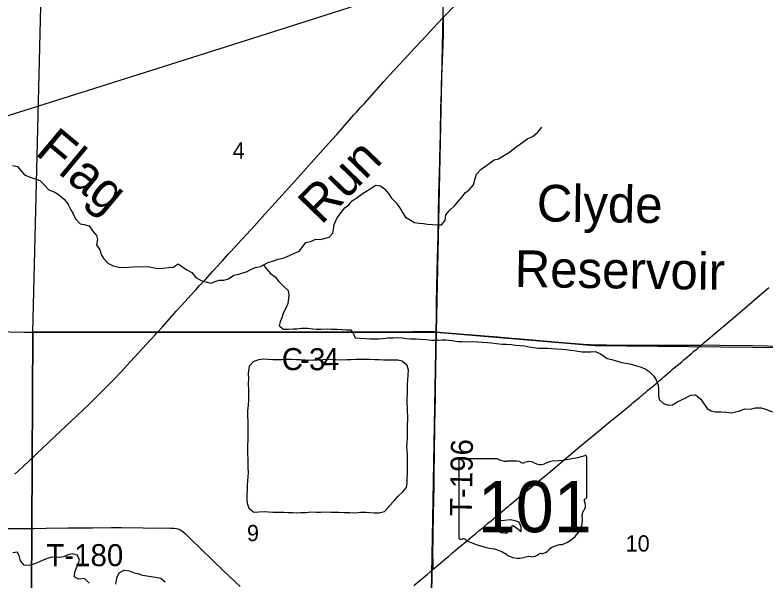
# Model space of a CAD drawing. Extents: x -8.5 to 18.7, y -20.3 to 7.
# Drawn here: x 3.109 to 6.975, y -13.956 to -11.043 of the extents above; entities that cross this region are included whole.
import ezdxf

# ---------------------------------------------------------------- set-up
doc = ezdxf.new("R2010")
doc.units = 0
for name, color, linetype in [('GM_X_County_Road', 7, 'Continuous'), ('GM_X_County_Road_Text', 7, 'Continuous'), ('GM_X_Minor_Lake', 7, 'Continuous'), ('GM_X_Minor_Lake_Text', 7, 'Continuous'), ('GM_X_Minor_River', 7, 'Continuous'), ('GM_X_Minor_River_Text', 7, 'Continuous'), ('GM_X_Rail_Line', 7, 'Continuous'), ('GM_X_Section', 7, 'Continuous'), ('GM_X_Section_Text', 7, 'Continuous'), ('GM_X_State_Location', 7, 'Continuous'), ('GM_X_State_Route', 7, 'Continuous'), ('GM_X_State_Shield', 7, 'Continuous'), ('GM_X_Township_Road', 7, 'Continuous'), ('GM_X_Township_Road_Text', 7, 'Continuous')]:
    doc.layers.add(name, color=color, linetype=linetype)

msp = doc.modelspace()

# ---------------------------------------------------------------- linework, layer by layer
at = {"layer": 'GM_X_County_Road'}
for points in [[(3.0069, -12.6754), (3.1591, -12.6774), (3.2088, -12.678), (3.2673, -12.6781), (3.3506, -12.6786), (3.3928, -12.6786), (3.4376, -12.6788), (3.4761, -12.6789), (3.4922, -12.6789), (3.5146, -12.6787), (3.5233, -12.6786), (3.537, -12.6783), (3.5754, -12.6787), (3.6127, -12.6782), (3.6782, -12.6782), (3.7482, -12.6772), (3.839, -12.6772), (3.8443, -12.6773)], [(3.8443, -12.6773), (3.9136, -12.6777), (4.0417, -12.6773), (4.1747, -12.6773), (4.2468, -12.6772), (4.3438, -12.6767), (4.4582, -12.6767), (4.5552, -12.6766), (4.6074, -12.6769), (4.7466, -12.677), (4.8535, -12.6762), (4.9207, -12.6761), (5.0052, -12.6759), (5.1557, -12.6755), (5.2203, -12.6751), (5.2689, -12.6755), (5.2805, -12.6762)], [(5.2805, -12.6762), (5.2969, -12.6779), (5.3167, -12.6796), (5.4209, -12.6881), (5.5981, -12.7028), (5.6699, -12.709), (5.738, -12.7149), (5.9114, -12.7301), (6.0402, -12.7408), (6.0761, -12.7426), (6.2401, -12.7444), (6.337, -12.7445), (6.4265, -12.7447), (6.4675, -12.7446), (6.5334, -12.7445), (6.6204, -12.7448), (6.6378, -12.7449), (6.6474, -12.7448)], [(6.6474, -12.7448), (6.6725, -12.7443), (6.741, -12.7448), (6.9101, -12.7471), (6.9884, -12.7484), (7.2047, -12.7508), (7.3352, -12.7531), (7.4089, -12.7537)]]:
    msp.add_lwpolyline(points, dxfattribs=at)
at = {"layer": 'GM_X_Minor_Lake'}
for points in [[(4.7452, -12.8204), (4.7195, -12.8195), (4.6983, -12.8209), (4.6695, -12.8223), (4.6476, -12.8229), (4.6279, -12.8235), (4.6075, -12.8227), (4.5802, -12.8217), (4.5583, -12.8216), (4.5341, -12.8192), (4.5076, -12.8198), (4.4857, -12.8205), (4.4584, -12.8211), (4.4387, -12.8202), (4.4145, -12.8185), (4.3926, -12.8169), (4.3646, -12.8205), (4.3373, -12.831), (4.3167, -12.8536), (4.3128, -12.8794)], [(5.0352, -13.58), (5.0389, -13.576), (5.0618, -13.5496), (5.0846, -13.524), (5.1075, -13.5028), (5.1273, -13.4794), (5.1312, -13.4544), (5.1313, -13.4347), (5.1322, -13.4089), (5.1325, -13.3642), (5.1334, -13.3369), (5.1328, -13.3171), (5.1307, -13.2876), (5.13, -13.2671), (5.1309, -13.2481), (5.1333, -13.2208), (5.1327, -13.1943), (5.1321, -13.1715), (5.133, -13.1503), (5.1338, -13.1313), (5.134, -13.1124), (5.1333, -13.0873), (5.1327, -13.0683), (5.1313, -13.0441), (5.1315, -13.019), (5.1324, -12.9925), (5.1325, -12.9682), (5.1334, -12.9485), (5.1351, -12.9235), (5.1367, -12.8977), (5.1376, -12.8742), (5.1302, -12.8506), (5.1053, -12.8285), (5.0827, -12.8223), (5.0085, -12.8219), (4.9873, -12.821), (4.9646, -12.8209), (4.9382, -12.82), (4.914, -12.8191), (4.889, -12.8189), (4.8686, -12.8196), (4.8398, -12.8202), (4.8194, -12.8216), (4.7883, -12.8222), (4.7649, -12.8205), (4.7452, -12.8204)], [(4.3128, -12.8794), (4.312, -12.8908), (4.3126, -12.9181), (4.3116, -12.9469), (4.3122, -12.9735), (4.3128, -13.0008), (4.3127, -13.0296), (4.3118, -13.0546), (4.3086, -13.0834), (4.3084, -13.1107), (4.309, -13.1365), (4.3096, -13.1676), (4.3102, -13.1919), (4.3101, -13.2124), (4.3092, -13.2351), (4.3083, -13.2602), (4.308, -13.3095), (4.3094, -13.3292), (4.31, -13.3489), (4.3099, -13.3785), (4.3105, -13.3998), (4.3096, -13.4248), (4.3087, -13.4453), (4.3063, -13.4665), (4.3062, -13.4945), (4.3053, -13.5143), (4.3051, -13.5416), (4.3065, -13.5605), (4.314, -13.5849), (4.3403, -13.6055), (4.3668, -13.6049), (4.3933, -13.6035), (4.416, -13.6044), (4.4387, -13.606), (4.4955, -13.6064), (4.5151, -13.608), (4.5393, -13.6081), (4.5628, -13.609), (4.5832, -13.6084), (4.6105, -13.6085), (4.6347, -13.6049), (4.6634, -13.6058), (4.6846, -13.6059), (4.7126, -13.6053), (4.7368, -13.607), (4.7588, -13.6056), (4.7792, -13.6072), (4.8057, -13.6073), (4.8352, -13.6083), (4.8639, -13.6092), (4.8897, -13.6055), (4.9192, -13.6065), (4.9389, -13.6073), (4.9616, -13.6097), (4.9873, -13.6106), (5.0138, -13.6024), (5.0352, -13.58)], [(5.7123, -13.6672), (5.7081, -13.6572), (5.6877, -13.651), (5.662, -13.6463), (5.6325, -13.6492), (5.6068, -13.6505), (5.5937, -13.6793), (5.6125, -13.712)], [(5.6125, -13.712), (5.6405, -13.7144), (5.661, -13.6994), (5.6747, -13.6737), (5.6966, -13.6897), (5.7177, -13.7065), (5.7186, -13.6823), (5.7123, -13.6672)]]:
    msp.add_lwpolyline(points, dxfattribs=at)
at = {"layer": 'GM_X_Minor_River'}
for points in [[(4.6322, -12.2099), (4.6595, -12.1979), (4.6837, -12.2003), (4.7035, -12.1944), (4.7285, -12.1892), (4.7475, -12.1681), (4.7506, -12.1476), (4.7553, -12.1234), (4.7691, -12.0923), (4.7844, -12.0697), (4.8096, -12.0364), (4.8308, -12.0221), (4.8476, -12.0018), (4.8734, -11.9845), (4.8993, -11.9649), (4.9182, -11.9536), (4.9403, -11.9386), (4.9699, -11.9198), (4.9926, -11.9237), (5.0137, -11.939), (5.034, -11.9634), (5.0505, -11.987), (5.0753, -12.0137), (5.0948, -12.0403), (5.1076, -12.0609), (5.1226, -12.0845), (5.1489, -12.1005), (5.1693, -12.112), (5.192, -12.1167), (5.2154, -12.1176), (5.2351, -12.1208), (5.2865, -12.1241), (5.3085, -12.1242), (5.3268, -12.1023), (5.3307, -12.0727), (5.3475, -12.0531), (5.3764, -12.0252), (5.3954, -12.0033), (5.413, -11.9822), (5.4313, -11.9588), (5.4503, -11.9437), (5.4724, -11.918), (5.4793, -11.8931), (5.4878, -11.8643), (5.5129, -11.8371), (5.535, -11.8228), (5.554, -11.8093), (5.579, -11.7897), (5.6025, -11.7838), (5.6322, -11.7657), (5.658, -11.7507), (5.6853, -11.7281), (5.7264, -11.698), (5.7522, -11.6792), (5.7788, -11.6687), (5.8046, -11.6468), (5.8259, -11.6219)], [(3.0969, -11.8182), (3.1218, -11.8237), (3.1376, -11.8427), (3.1587, -11.8663), (3.1851, -11.8786), (3.21, -11.8856), (3.238, -11.8964), (3.2598, -11.9185), (3.2846, -11.9444), (3.3148, -11.9567), (3.3397, -11.9713), (3.3638, -11.9942), (3.384, -12.0201), (3.3975, -12.0475), (3.4087, -12.0672), (3.4214, -12.0931), (3.4455, -12.1198), (3.4652, -12.1229), (3.4916, -12.1307), (3.5081, -12.155), (3.5299, -12.1802), (3.5343, -12.1999), (3.5289, -12.2272), (3.5469, -12.2539), (3.5558, -12.2805), (3.5678, -12.2995), (3.5888, -12.3231), (3.616, -12.3362), (3.644, -12.3432), (3.6704, -12.3456), (3.6969, -12.3427), (3.7204, -12.3406), (3.7514, -12.34), (3.7726, -12.3408), (3.7983, -12.3402), (3.818, -12.3449), (3.8452, -12.3504), (3.874, -12.3475), (3.9012, -12.3454), (3.9247, -12.3425), (3.9505, -12.3259), (3.9731, -12.3405), (3.9957, -12.3573), (4.0206, -12.3711), (4.0417, -12.397), (4.0696, -12.4123), (4.0923, -12.4185), (4.1187, -12.4255), (4.1407, -12.4173), (4.1619, -12.4098), (4.1861, -12.4107), (4.2104, -12.404), (4.237, -12.3844), (4.2635, -12.3785), (4.2832, -12.3718), (4.3022, -12.3666), (4.3211, -12.3561), (4.3469, -12.3456), (4.375, -12.3397), (4.3977, -12.3277), (4.4182, -12.3179), (4.4432, -12.3112), (4.4637, -12.3023), (4.4842, -12.2986), (4.5084, -12.2889), (4.5274, -12.2806), (4.5494, -12.2716), (4.5744, -12.2612), (4.5904, -12.2415), (4.608, -12.2166), (4.6322, -12.2099)], [(4.3903, -12.3316), (4.4021, -12.3489), (4.4262, -12.3749), (4.4503, -12.3932), (4.4699, -12.4168), (4.4932, -12.4405), (4.5172, -12.4641), (4.5209, -12.4854), (4.5193, -12.5051), (4.5153, -12.5301), (4.5069, -12.5505), (4.4939, -12.5763), (4.4846, -12.6043), (4.477, -12.6247), (4.4708, -12.6452), (4.4934, -12.6635), (4.5191, -12.6629), (4.5426, -12.6615), (4.563, -12.6608), (4.5865, -12.6572), (4.6175, -12.6581), (4.644, -12.6605), (4.6644, -12.6622), (4.6863, -12.6623), (4.7189, -12.6617), (4.7408, -12.6626), (4.7681, -12.662), (4.7953, -12.6637), (4.8203, -12.6668), (4.8407, -12.6654), (4.8542, -12.686), (4.8632, -12.7073), (4.8881, -12.7089), (4.9191, -12.7114), (4.9388, -12.713), (4.9638, -12.7124), (4.9842, -12.7125), (5.0054, -12.7104), (5.0311, -12.7082), (5.0591, -12.7069), (5.0826, -12.7055), (5.1068, -12.7071), (5.128, -12.7111), (5.1476, -12.7134), (5.1779, -12.7129), (5.2021, -12.7145), (5.2271, -12.7162), (5.2558, -12.7186), (5.2906, -12.7203), (5.3103, -12.7181), (5.3307, -12.7183), (5.3617, -12.7215), (5.3927, -12.7262), (5.4124, -12.7271), (5.4359, -12.7272), (5.4661, -12.7258), (5.4949, -12.7283), (5.5183, -12.7299), (5.5448, -12.7308), (5.5652, -12.7332), (5.5917, -12.7372), (5.6204, -12.7396), (5.6424, -12.7405), (5.6681, -12.7422), (5.6885, -12.7453), (5.7142, -12.747), (5.7354, -12.7486), (5.7596, -12.7533), (5.7822, -12.7565), (5.8102, -12.7604), (5.8306, -12.7613), (5.8534, -12.7606), (5.876, -12.763), (5.901, -12.7639), (5.9282, -12.7664), (5.9502, -12.768), (5.9721, -12.7704), (6.0016, -12.7744), (6.0333, -12.7799), (6.0538, -12.78), (6.078, -12.7794), (6.1014, -12.778), (6.1279, -12.7895), (6.1625, -12.8132), (6.186, -12.8187), (6.2132, -12.8271), (6.2366, -12.8349), (6.2577, -12.838), (6.2849, -12.8435), (6.3084, -12.8497), (6.3318, -12.8566), (6.3574, -12.8666), (6.3786, -12.8804), (6.4019, -12.9048), (6.4146, -12.9246), (6.4243, -12.9512), (6.4265, -12.9702), (6.4263, -13.0028), (6.4292, -13.0256), (6.4525, -13.0462), (6.4782, -13.0554)], [(6.4782, -13.0554), (6.4994, -13.0533), (6.5206, -13.0398), (6.5457, -13.0278), (6.5647, -13.018), (6.592, -13.0022), (6.6177, -13.0016), (6.6441, -13.023), (6.6583, -13.0443), (6.6778, -13.0717), (6.6974, -13.084), (6.7179, -13.0887), (6.7489, -13.0896), (6.7761, -13.0913), (6.8011, -13.0937), (6.8408, -13.0858)], [(6.8408, -13.0858), (6.8711, -13.0735), (6.8999, -13.0744), (6.9272, -13.0677), (6.956, -13.0686), (6.9832, -13.0771), (7.0044, -13.0863), (7.0286, -13.0917), (7.0513, -13.0895), (7.0778, -13.0927), (7.1028, -13.0974), (7.127, -13.1096)], [(3.4922, -13.9724), (3.4674, -13.948), (3.4379, -13.9516), (3.4137, -13.9401), (3.4199, -13.9098), (3.4322, -13.8818), (3.4422, -13.8538), (3.4318, -13.8287), (3.4053, -13.8209), (3.3818, -13.8269), (3.3598, -13.8366), (3.3386, -13.8403), (3.3137, -13.8379), (3.2902, -13.84), (3.2583, -13.852), (3.2356, -13.8632), (3.2106, -13.8722), (3.1855, -13.8812), (3.1575, -13.8795), (3.1372, -13.8574), (3.1328, -13.8369), (3.1224, -13.8133), (3.0989, -13.8169)], [(3.8835, -13.967), (3.8616, -13.9487), (3.8336, -13.944), (3.7989, -13.9377), (3.7686, -13.933), (3.7445, -13.9245), (3.7248, -13.9214), (3.6991, -13.9114), (3.6704, -13.9066), (3.6454, -13.9209), (3.6323, -13.9474), (3.6276, -13.9769)]]:
    msp.add_lwpolyline(points, dxfattribs=at)
at = {"layer": 'GM_X_Rail_Line'}
msp.add_lwpolyline([(3.0526, -11.567), (3.135, -11.5413), (3.8099, -11.3283), (4.4114, -11.1374), (4.5567, -11.0915), (4.9083, -10.98)], dxfattribs=at)
at = {"layer": 'GM_X_Section'}
for points in [[(3.3838, -10.7208), (5.3205, -10.7946), (5.2797, -12.6788), (3.2006, -12.6781), (3.25, -10.7172)], [(1.1777, -12.6489), (3.2006, -12.6781), (3.1911, -14.698), (1.1578, -14.6567)], [(3.2006, -12.6781), (5.2797, -12.6788), (5.2437, -14.6964), (3.1911, -14.698)], [(5.2797, -12.6788), (6.0987, -12.7461), (7.3966, -12.7605), (7.3681, -14.7705), (6.0431, -14.7415), (5.2437, -14.6964)]]:
    msp.add_lwpolyline(points, close=True, dxfattribs=at)
at = {"layer": 'GM_X_State_Route'}
msp.add_lwpolyline([(5.1657, -13.9852), (5.2354, -13.9253), (5.2653, -13.9), (5.2939, -13.8759), (5.3282, -13.8471), (5.3434, -13.8343), (5.3644, -13.8168), (5.3892, -13.7961), (5.4169, -13.773), (5.4331, -13.7594), (5.4599, -13.7372), (5.4857, -13.7157), (5.5028, -13.7013), (5.5219, -13.6854), (5.5475, -13.6637), (5.5638, -13.6502), (5.5751, -13.6405), (5.5934, -13.6256), (5.6161, -13.6063), (5.6306, -13.5945), (5.638, -13.5879), (5.6514, -13.5768), (5.6579, -13.571), (5.6675, -13.5632), (5.6985, -13.5369), (5.7052, -13.5314), (5.8124, -13.4426), (5.8709, -13.3944), (5.9405, -13.3362), (6.0297, -13.2607), (6.1256, -13.1815), (6.1689, -13.1461), (6.2302, -13.0953), (6.2765, -13.0576), (6.2849, -13.0504), (6.2877, -13.0481), (6.2979, -13.0395), (6.3118, -13.0282), (6.3278, -13.0148), (6.3325, -13.0109), (6.3373, -13.0069), (6.343, -13.0022), (6.3515, -12.995), (6.361, -12.9869), (6.3705, -12.979), (6.38, -12.9709), (6.3866, -12.9653), (6.3999, -12.9541), (6.4143, -12.9422), (6.4296, -12.9295), (6.438, -12.9221), (6.4466, -12.915), (6.4542, -12.9086), (6.4685, -12.8966), (6.4768, -12.8891), (6.4882, -12.8796), (6.4994, -12.8697), (6.5231, -12.8497), (6.5461, -12.8307), (6.5563, -12.8216), (6.5772, -12.804), (6.5878, -12.7954), (6.5982, -12.7866), (6.6076, -12.7784), (6.6257, -12.7633), (6.6381, -12.7529), (6.6474, -12.7448), (6.6549, -12.7382), (6.6613, -12.7323), (6.6801, -12.7162), (6.6934, -12.7052), (6.7048, -12.6957), (6.7229, -12.6806), (6.7382, -12.6678), (6.7484, -12.6587), (6.7646, -12.6452), (6.7786, -12.6328), (6.792, -12.6218), (6.8235, -12.5954), (6.9957, -12.4487)], dxfattribs=at)
at = {"layer": 'GM_X_State_Shield'}
for p, q in [((5.5967, -13.331), (5.4037, -13.331)), ((6.0564, -13.5304), (6.0564, -13.3211)), ((5.3972, -13.3379), (5.3972, -13.7381)), ((6.0563, -13.5304), (6.0564, -13.5304))]:
    msp.add_line(p, q, dxfattribs=at)
for centre, major_axis, start_param, end_param in [((5.4048, -13.337), (0.00764, 0), 1.712693, 3.28349), ((5.6427, -13.2845), (0.0741, 0), 4.042523, 4.731795), ((5.8216, -12.7853), (0.699, 0), 4.814394, 5.042369), ((6.0491, -13.3202), (0.00734, 0), 6.141152, 7.989035), ((5.6673, -13.5557), (0.2659, 0), 1.404758, 1.657858), ((5.7276, -13.3349), (0.0214, 0), 3.836095, 5.185415), ((5.759, -13.3812), (0.0444, 0), 0.950623, 2.079405), ((5.8163, -13.3177), (0.0534, 0), 4.081561, 5.145723), ((5.9107, -13.4532), (0.1406, 0), 1.699011, 2.107814), ((6.0485, -13.5312), (0.00785, 0), 5.05454, 6.418171), ((6.0547, -13.5458), (0.0114, 0), 1.883978, 3.671073), ((5.9824, -13.5723), (0.0682, 0), 5.934695, 6.695948), ((6.0827, -13.618), (0.0496, 0), 2.387724, 3.262537), ((5.8607, -13.6447), (0.1748, 0), 5.101752, 6.440018), ((5.4048, -13.739), (0.0077, 0), 3.00124, 4.508301), ((5.406, -13.698), (0.0588, 0), 4.665946, 4.897461), ((5.418, -13.7612), (0.0212, 0), 0.519207, 1.627899), ((5.6857, -13.4016), (0.5048, 0), 4.195997, 4.488961), ((5.5352, -13.9179), (0.1579, 0), 0.823519, 1.323587), ((5.9344, -13.8505), (0.0958, 0), 1.647645, 2.488434), ((5.706, -13.7632), (0.1002, 0), 4.026481, 4.996735), ((5.7639, -13.9016), (0.0824, 0), 1.495662, 1.94098), ((5.7712, -13.7932), (0.0534, 0), 4.691044, 5.507374), ((5.8195, -13.8319), (0.015, 0), 1.147584, 2.315152), ((5.8131, -13.7769), (0.0565, 0), 4.937069, 5.64225)]:
    msp.add_ellipse(centre, major_axis=major_axis, ratio=0.8, start_param=start_param, end_param=end_param, dxfattribs=at)
at = {"layer": 'GM_X_Township_Road'}
for points in [[(5.3184, -11.0539), (5.3256, -11.0462), (5.3716, -10.999), (5.4231, -10.9468), (5.4448, -10.9245), (5.4647, -10.9041), (5.4868, -10.8822), (5.5053, -10.8638), (5.5353, -10.8341), (5.5537, -10.816), (5.5688, -10.8011)], [(3.8443, -12.6773), (3.8456, -12.6758), (3.8691, -12.6501), (3.9075, -12.6077), (3.9404, -12.5704), (3.9666, -12.5421), (4.0183, -12.485), (4.0346, -12.4667), (4.0412, -12.4595), (4.0612, -12.4378), (4.0906, -12.4058), (4.1288, -12.3633), (4.1714, -12.3166), (4.1782, -12.3097), (4.21, -12.275), (4.2234, -12.2604), (4.2527, -12.2283), (4.2822, -12.1963), (4.3433, -12.1292), (4.3977, -12.0695), (4.4865, -11.972), (4.5171, -11.9377), (4.5519, -11.8992), (4.5957, -11.85), (4.6367, -11.805), (4.6839, -11.7521), (4.7436, -11.6854), (4.769, -11.6581), (4.7931, -11.6313), (4.8118, -11.6096), (4.8341, -11.5834), (4.8564, -11.558), (4.8697, -11.5434), (4.8905, -11.5204), (4.9104, -11.4983), (4.9228, -11.4845), (5.0107, -11.3864), (5.0422, -11.3512), (5.0622, -11.3291), (5.1134, -11.2732), (5.1729, -11.2097), (5.2287, -11.1496), (5.2873, -11.0868), (5.3184, -11.0539)], [(5.2805, -12.6762), (5.2803, -12.6748), (5.2815, -12.5927), (5.2825, -12.538), (5.2845, -12.4399), (5.2875, -12.3007), (5.2886, -12.236), (5.29, -12.1776), (5.2924, -12.0708), (5.2945, -11.9701), (5.2978, -11.8508), (5.299, -11.7961), (5.3017, -11.7005), (5.3021, -11.6756), (5.3031, -11.6344), (5.3035, -11.6044), (5.304, -11.5753), (5.3051, -11.5377), (5.3051, -11.509), (5.3057, -11.4941), (5.3063, -11.4805), (5.3074, -11.4372), (5.308, -11.3998), (5.3115, -11.3179), (5.3157, -11.1973), (5.3179, -11.1402), (5.3189, -11.0881), (5.3185, -11.0633), (5.3184, -11.0539)], [(3.1081, -13.4108), (3.1535, -13.3687), (3.1809, -13.3433), (3.1953, -13.3296), (3.2062, -13.3194), (3.2279, -13.2989), (3.2449, -13.2826), (3.2858, -13.2444), (3.4007, -13.1361), (3.4876, -13.0524), (3.5887, -12.953), (3.6175, -12.9238), (3.657, -12.8824), (3.7049, -12.8301), (3.8076, -12.7185), (3.833, -12.6895), (3.8443, -12.6773)], [(5.2653, -13.9), (5.2645, -13.8832), (5.2641, -13.8738), (5.2639, -13.8181), (5.2654, -13.7423), (5.2673, -13.6006), (5.2682, -13.5596), (5.2696, -13.4527), (5.2702, -13.3856), (5.2714, -13.3234), (5.2723, -13.2662), (5.2739, -13.2041), (5.2742, -13.1569), (5.2761, -13.0115), (5.277, -12.9643), (5.2779, -12.8599), (5.2783, -12.8226), (5.2798, -12.7455), (5.2805, -12.6762)], [(3.0608, -13.6901), (3.13, -13.6906), (3.2066, -13.6898), (3.27, -13.6891), (3.3819, -13.6878), (3.4291, -13.6871), (3.4391, -13.6869), (3.5087, -13.687), (3.6068, -13.6862), (3.6582, -13.686), (3.7698, -13.6876), (3.8182, -13.6881), (3.8331, -13.6878), (3.9102, -13.6882), (3.9275, -13.6889), (3.9409, -13.6905), (3.9493, -13.6921), (3.9562, -13.6947), (3.9614, -13.697), (3.9683, -13.7009), (3.9753, -13.7068), (3.9864, -13.7166), (4.0076, -13.7375), (4.0156, -13.7453), (4.0672, -13.7958), (4.1271, -13.8537), (4.1863, -13.9101), (4.2702, -13.9901)]]:
    msp.add_lwpolyline(points, dxfattribs=at)

# ---------------------------------------------------------------- texts
at = {"layer": 'GM_X_County_Road_Text'}
for s, rotation, p in [('C', 359.637, (4.4844, -12.8735)), ('3', 359.837, (4.6248, -12.8743)), ('4', 0.6224, (4.6965, -12.8745)), ('-', 359.6781, (4.5778, -12.8741))]:
    msp.add_text(s, height=0.1136, rotation=rotation, dxfattribs=at).set_placement(p)
at = {"layer": 'GM_X_Minor_Lake_Text'}
for s, rotation, p in [('Clyde', 359.2114, (5.7984, -12.1069)), ('Reservoir', 359.2116, (5.6842, -12.4451))]:
    msp.add_text(s, height=0.18949, rotation=rotation, dxfattribs=at).set_placement(p)
at = {"layer": 'GM_X_Minor_River_Text'}
for s, rotation, p in [('Flag', 320.2003, (3.2082, -11.7578)), ('Run', 45.8399, (4.6882, -12.1294))]:
    msp.add_text(s, height=0.1895, rotation=rotation, dxfattribs=at).set_placement(p)
at = {"layer": 'GM_X_Section_Text'}
for s, height, p in [('4', 0.0837, (4.2315, -11.7836)), ('9', 0.0837, (4.3048, -13.7559)), ('10', 0.08371, (6.2565, -13.8093))]:
    msp.add_text(s, height=height, rotation=0, dxfattribs=at).set_placement(p)
at = {"layer": 'GM_X_State_Location'}
for s in ['s', 'r']:
    msp.add_text(s, height=0.000379, dxfattribs=at).set_placement((5.7194, -13.5646))
msp.add_text('101', height=0.000379, rotation=0, dxfattribs=at).set_placement((5.5857, -13.5922))
at = {"layer": 'GM_X_State_Shield'}
msp.add_text('101', height=0.26367, dxfattribs=at).set_placement((5.4943, -13.7099))
at = {"layer": 'GM_X_Township_Road_Text'}
for s, rotation, p in [('T-196', 89.158, (5.4645, -13.6272)), ('T-180', 0, (3.2707, -13.8849))]:
    msp.add_text(s, height=0.11364, rotation=rotation, dxfattribs=at).set_placement(p)

doc.saveas('drawing.dxf')
